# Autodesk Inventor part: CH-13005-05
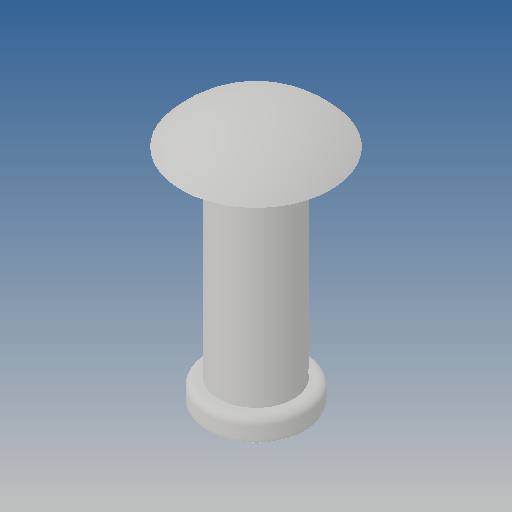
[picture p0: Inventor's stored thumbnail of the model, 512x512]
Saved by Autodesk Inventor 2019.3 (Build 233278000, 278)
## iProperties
Created: 2012-09
Part Number: CH-13005-05
Material: Ogólny
Document SubType Name: Modeling
Designer: CADENGINEERING4
Density: 1 g/cm^3
Appearance: Domyślna
Author: CADENGINEERING4
Revision Number: ÈÎºÎ
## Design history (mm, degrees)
feature "ÇÐ³ý-Ðý×ª1"
node "Bryła1"
